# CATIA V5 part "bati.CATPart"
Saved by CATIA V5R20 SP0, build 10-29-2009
Part number: bati
Bounding box of the stored display mesh (mm): x -300 to 185, y 132.966 to 292.794, z 45.492 to 205.454
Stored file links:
  C:\Users\Mike-7\Desktop\MMS_GR3\bfoltzer\CFAO_bfoltzer\bati.CATPart
  D:\ecole\thinkmotion\Eolienne.CATProduct
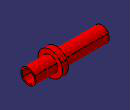
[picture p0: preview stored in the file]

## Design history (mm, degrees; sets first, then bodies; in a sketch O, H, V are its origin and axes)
Set1
  Plane1: linked copy from another document
  Point1 to Point8: linked copy from another document
  Line1 "Axe de rotation": linked copy from another document
Body1 (main body)
  Sketch1 on Plane1, origin (0, 0, 125.4731), H (1, 0, 0), V (0, 1, 0)
    point P1 (-300, 262.8803)
    line L1 (-300, 262.8803) -> (-300, 252.8803)
    point P2 (-300, 252.8803)
    line L2 (-300, 252.8803) -> (185, 252.8803)
    point P3 (185, 252.8803)
    line L3 (185, 252.8803) -> (185, 262.8803)
    point P4 (185, 262.8803)
    line L4 (185, 262.8803) -> (40, 262.8803)
    point P5 (40, 262.8803)
    line L5 (40, 262.8803) -> (40, 292.8803)
    point P6 (40, 292.8803)
    line L6 (40, 292.8803) -> (0, 292.8803)
    point P7 (0, 292.8803)
    line L7 (0, 292.8803) -> (0, 262.8803)
    point P8 (0, 262.8803)
    line L8 (0, 262.8803) -> (-300, 262.8803)
    reference projected point E1 (40, 262.8803) from Point2
    reference projected point E2 (185, 262.8803) from Point3
    reference projected point E3 (185, 252.8803) from Point4
    reference projected point E4 (40, 292.8803) from Point1
    reference projected point E5 (0, 292.8803) from Point5
    reference projected point E6 (0, 262.8803) from Point6
    reference projected point E7 (-300, 252.8803) from Point7
    reference projected point E8 (-300, 262.8803) from Point8
    vertical: L1 V, L3 V, L5 V, L7 V
    horizontal: L2 H, L4 H, L6 H
    coincidence: P5 E1, P4 E2, P3 E3, P6 E4, P7 E5, P8 E6, P2 E7, P1 E8
  Shaft1: profile Sketch1, axis Line1, angle 360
